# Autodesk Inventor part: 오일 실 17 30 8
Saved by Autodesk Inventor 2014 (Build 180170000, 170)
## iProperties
Created: 2026-06
Part Number: 오일 실 17 30 8
Material: 고무
Document SubType Name: Modeling
Designer: dg
Density: 0.93 g/cm^3
Appearance: 고무 - 검은색 - 버전 1.1
Mass: 1.6913 g
Surface Area: 28.0102 cm^2
Volume: 1.81861 cm^3
Author: jhkim
Description: 오일-실
Creation Date: 2026-05-29
Sending System: Autodesk Inventor 2027
Preprocessor: ST-DEVELOPER v20.1
Author: dg
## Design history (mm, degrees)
node "오일 실 17 30 81"
body "Solid1"
node "기준1"
